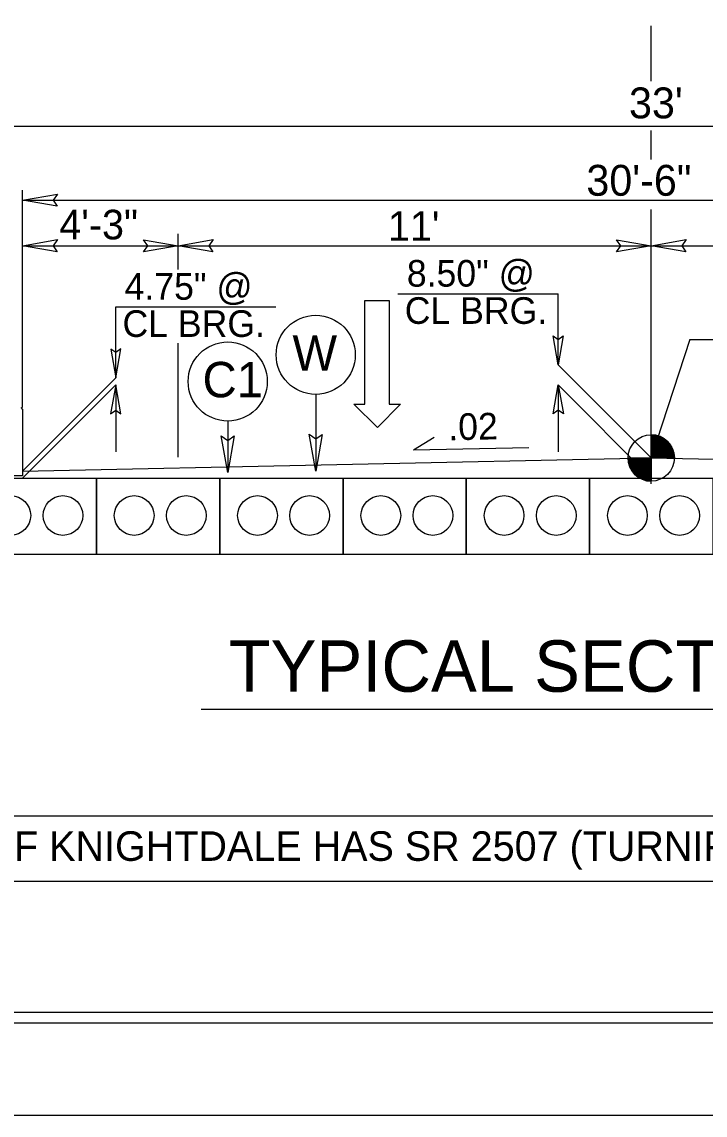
# Model space of a CAD drawing. Extents: x 693533 to 693723, y 486383 to 486493.
# Drawn here: x 693602.77 to 693619.39, y 486383.31 to 486409.89 of the extents above; entities that cross this region are included whole.
import ezdxf

# ---------------------------------------------------------------- set-up
doc = ezdxf.new("R2010")
doc.units = 0
for name, color, linetype in [('Default', 7, 'Continuous'), ('Old_Level_1', 7, 'Continuous'), ('Old_Level_11', 7, 'Continuous'), ('Old_Level_28', 7, 'Continuous'), ('Old_Level_3', 7, 'Continuous'), ('Prop Dimension', 7, 'Continuous'), ('Prop Lane Arrow CELL', 7, 'Continuous'), ('Sheet Cutting Line CELL', 7, 'Continuous'), ('Sheet Plot Border Inside CELL', 7, 'Continuous'), ('Sheet Plot Border Outside CELL', 7, 'Continuous'), ('Sheet Typical CELL', 7, 'Continuous'), ('Typical Bridge Rail Two Bar CELL', 7, 'Continuous'), ('Typical ID Circle CELL', 7, 'Continuous'), ('Typical Pavement Slope Information CELL', 7, 'Continuous'), ('Typical Terminator CELL', 7, 'Continuous'), ('Typical Text ID Circle CELL', 7, 'Continuous')]:
    doc.layers.add(name, color=color, linetype=linetype)

msp = doc.modelspace()

# ---------------------------------------------------------------- linework, layer by layer
at = {"layer": 'Default'}
for p, q in [((693618.081, 486408.451), (693618.081, 486409.801)), ((693618.081, 486406.545), (693618.081, 486407.256)), ((693618.081, 486398.664), (693618.081, 486405.329))]:
    msp.add_line(p, q, dxfattribs=at)
at = {"layer": 'Old_Level_1'}
msp.add_line((693607.128, 486393.188), (693629.755, 486393.188), dxfattribs=at)
msp.add_lwpolyline([(693595.018, 486390.588), (693644.204, 486390.588), (693644.204, 486388.993), (693595.018, 486388.993)], close=True, dxfattribs=at)
at = {"layer": 'Old_Level_28'}
for p, q in [((693601.581, 486407.359), (693634.581, 486407.359)), ((693602.787, 486400.52), (693602.787, 486405.801)), ((693602.787, 486405.557), (693633.374, 486405.557)), ((693606.574, 486403.872), (693606.574, 486404.74)), ((693602.787, 486404.451), (693606.574, 486404.451)), ((693606.574, 486404.451), (693618.081, 486404.451)), ((693618.081, 486404.451), (693629.081, 486404.451)), ((693606.574, 486399.312), (693606.574, 486402.086)), ((693619.016, 486402.168), (693618.081, 486399.291)), ((693619.016, 486402.168), (693623.462, 486402.168)), ((693618.081, 486399.291), (693618.081, 486399.853)), ((693602.787, 486398.972), (693618.081, 486399.291)), ((693617.518, 486399.291), (693618.081, 486399.291)), ((693618.079, 486398.728), (693618.081, 486399.291)), ((693618.081, 486399.291), (693618.079, 486398.728)), ((693618.081, 486399.291), (693633.374, 486398.972)), ((693618.643, 486399.291), (693618.081, 486399.291))]:
    msp.add_line(p, q, dxfattribs=at)
for points in [[(693603.631, 486405.412), (693602.787, 486405.557), (693603.636, 486405.707), (693603.528, 486405.557)], [(693603.631, 486404.305), (693602.787, 486404.451), (693603.636, 486404.601), (693603.528, 486404.451)], [(693605.731, 486404.596), (693606.574, 486404.451), (693605.726, 486404.301), (693605.834, 486404.451)], [(693607.418, 486404.305), (693606.574, 486404.451), (693607.423, 486404.601), (693607.315, 486404.451)], [(693617.237, 486404.596), (693618.081, 486404.451), (693617.232, 486404.301), (693617.34, 486404.451)], [(693618.924, 486404.305), (693618.081, 486404.451), (693618.929, 486404.601), (693618.821, 486404.451)], [(693601.581, 486398.804), (693604.581, 486398.804), (693604.581, 486396.944), (693601.581, 486396.944)], [(693604.581, 486398.804), (693607.581, 486398.804), (693607.581, 486396.944), (693604.581, 486396.944)], [(693607.581, 486398.804), (693610.581, 486398.804), (693610.581, 486396.944), (693607.581, 486396.944)], [(693610.581, 486398.804), (693613.581, 486398.804), (693613.581, 486396.944), (693610.581, 486396.944)], [(693613.581, 486398.804), (693616.581, 486398.804), (693616.581, 486396.944), (693613.581, 486396.944)], [(693616.581, 486398.804), (693619.581, 486398.804), (693619.581, 486396.944), (693616.581, 486396.944)]]:
    msp.add_lwpolyline(points, close=True, dxfattribs=at)
for points in [[(693618.086, 486399.853), (693618.086, 486399.853), (693618.086, 486399.291)], [(693618.097, 486399.853), (693618.097, 486399.291)], [(693618.108, 486399.852), (693618.108, 486399.291)], [(693618.119, 486399.852), (693618.119, 486399.291)], [(693618.131, 486399.851), (693618.131, 486399.291)], [(693618.142, 486399.849), (693618.142, 486399.291)], [(693618.153, 486399.848), (693618.153, 486399.291)], [(693618.164, 486399.847), (693618.164, 486399.291)], [(693618.176, 486399.846), (693618.176, 486399.291)], [(693618.187, 486399.843), (693618.187, 486399.291)], [(693618.198, 486399.841), (693618.198, 486399.291)], [(693618.209, 486399.838), (693618.209, 486399.291)], [(693618.221, 486399.836), (693618.221, 486399.291)], [(693618.232, 486399.832), (693618.232, 486399.291)], [(693618.243, 486399.829), (693618.243, 486399.291)], [(693618.254, 486399.826), (693618.254, 486399.291)], [(693618.266, 486399.822), (693618.266, 486399.291)], [(693618.277, 486399.818), (693618.277, 486399.291)], [(693618.288, 486399.813), (693618.288, 486399.291)], [(693618.299, 486399.808), (693618.299, 486399.291)], [(693618.311, 486399.803), (693618.311, 486399.291)], [(693618.322, 486399.798), (693618.322, 486399.291)], [(693618.333, 486399.793), (693618.333, 486399.291)], [(693618.344, 486399.787), (693618.344, 486399.291)], [(693618.356, 486399.781), (693618.356, 486399.291)], [(693618.367, 486399.774), (693618.367, 486399.291)], [(693618.378, 486399.768), (693618.378, 486399.291)], [(693618.389, 486399.761), (693618.389, 486399.291)], [(693618.401, 486399.753), (693618.401, 486399.291)], [(693618.412, 486399.744), (693618.412, 486399.291)], [(693618.423, 486399.737), (693618.423, 486399.291)], [(693618.434, 486399.728), (693618.434, 486399.291)], [(693618.446, 486399.718), (693618.446, 486399.291)], [(693618.457, 486399.708), (693618.457, 486399.291)], [(693618.468, 486399.698), (693618.468, 486399.291)], [(693618.479, 486399.687), (693618.479, 486399.291)], [(693618.491, 486399.676), (693618.491, 486399.291)], [(693618.502, 486399.663), (693618.502, 486399.291)], [(693618.513, 486399.649), (693618.513, 486399.291)], [(693618.524, 486399.636), (693618.524, 486399.291)], [(693618.536, 486399.621), (693618.536, 486399.291)], [(693618.547, 486399.604), (693618.547, 486399.291)], [(693618.558, 486399.587), (693618.558, 486399.291)], [(693618.569, 486399.568), (693618.569, 486399.291)], [(693618.581, 486399.548), (693618.581, 486399.291)], [(693618.592, 486399.524), (693618.592, 486399.291)], [(693618.603, 486399.498), (693618.603, 486399.291)], [(693618.614, 486399.467), (693618.614, 486399.291)], [(693618.626, 486399.428), (693618.626, 486399.291)], [(693618.637, 486399.371), (693618.637, 486399.291)], [(693617.521, 486399.291), (693617.521, 486399.229)], [(693617.532, 486399.291), (693617.532, 486399.163)], [(693617.543, 486399.291), (693617.543, 486399.123)], [(693617.554, 486399.291), (693617.554, 486399.089)], [(693617.566, 486399.291), (693617.566, 486399.063)], [(693617.577, 486399.291), (693617.577, 486399.039)], [(693617.588, 486399.291), (693617.588, 486399.018)], [(693617.599, 486399.291), (693617.599, 486398.998)], [(693617.611, 486399.291), (693617.611, 486398.981)], [(693617.622, 486399.291), (693617.622, 486398.964)], [(693617.633, 486399.291), (693617.633, 486398.949)], [(693617.644, 486399.291), (693617.644, 486398.936)], [(693617.656, 486399.291), (693617.656, 486398.922)], [(693617.667, 486399.291), (693617.667, 486398.909)], [(693617.678, 486399.291), (693617.678, 486398.897)], [(693617.689, 486399.291), (693617.689, 486398.886)], [(693617.701, 486399.291), (693617.701, 486398.876)], [(693617.712, 486399.291), (693617.712, 486398.866)], [(693617.723, 486399.291), (693617.723, 486398.856)], [(693617.734, 486399.291), (693617.734, 486398.847)], [(693617.746, 486399.291), (693617.746, 486398.838)], [(693617.757, 486399.291), (693617.757, 486398.831)], [(693617.768, 486399.291), (693617.768, 486398.823)], [(693617.779, 486399.291), (693617.779, 486398.816)], [(693617.791, 486399.291), (693617.791, 486398.808)], [(693617.802, 486399.291), (693617.802, 486398.802)], [(693617.813, 486399.291), (693617.813, 486398.796)], [(693617.824, 486399.291), (693617.824, 486398.789)], [(693617.836, 486399.291), (693617.836, 486398.784)], [(693617.847, 486399.291), (693617.847, 486398.779)], [(693617.858, 486399.291), (693617.858, 486398.774)], [(693617.869, 486399.291), (693617.869, 486398.769)], [(693617.881, 486399.291), (693617.881, 486398.764)], [(693617.892, 486399.291), (693617.892, 486398.761)], [(693617.903, 486399.291), (693617.903, 486398.757)], [(693617.914, 486399.291), (693617.914, 486398.753)], [(693617.926, 486399.291), (693617.926, 486398.751)], [(693617.937, 486399.291), (693617.937, 486398.747)], [(693617.948, 486399.291), (693617.948, 486398.744)], [(693617.959, 486399.291), (693617.959, 486398.742)], [(693617.971, 486399.291), (693617.971, 486398.739)], [(693617.982, 486399.291), (693617.982, 486398.737)], [(693617.993, 486399.291), (693617.993, 486398.736)], [(693618.004, 486399.291), (693618.004, 486398.733)], [(693618.016, 486399.291), (693618.016, 486398.732)], [(693618.027, 486399.291), (693618.027, 486398.731)], [(693618.038, 486399.291), (693618.038, 486398.729)], [(693618.049, 486399.291), (693618.049, 486398.729)], [(693618.061, 486399.291), (693618.061, 486398.728)], [(693618.072, 486399.291), (693618.072, 486398.728), (693618.072, 486398.728)]]:
    msp.add_lwpolyline(points, dxfattribs=at)
for centre, radius in [((693618.08, 486399.291), 0.563), ((693602.501, 486397.892), 0.483), ((693603.769, 486397.892), 0.483), ((693605.501, 486397.892), 0.483), ((693606.769, 486397.892), 0.483), ((693608.501, 486397.892), 0.483), ((693609.769, 486397.892), 0.483), ((693611.501, 486397.892), 0.483), ((693612.769, 486397.892), 0.483), ((693614.501, 486397.892), 0.483), ((693615.769, 486397.892), 0.483), ((693617.501, 486397.892), 0.483), ((693618.769, 486397.892), 0.483)]:
    msp.add_circle(centre, radius, dxfattribs=at)
for start, end in [(359.9905, 89.9905), (179.9905, 269.9905)]:
    msp.add_arc((693618.08, 486399.291), 0.563, start, end, dxfattribs=at)
at = {"layer": 'Prop Dimension'}
for p, q in [((693611.917, 486403.281), (693615.816, 486403.281)), ((693615.816, 486401.555), (693615.816, 486403.281)), ((693605.052, 486401.237), (693605.052, 486402.962)), ((693605.052, 486402.962), (693608.95, 486402.962)), ((693615.816, 486401.555), (693618.081, 486399.291)), ((693605.052, 486401.237), (693602.787, 486398.972)), ((693605.052, 486401.069), (693602.787, 486398.804)), ((693605.052, 486401.069), (693605.052, 486399.439)), ((693615.816, 486401.069), (693618.081, 486398.804)), ((693615.816, 486401.069), (693615.816, 486399.439))]:
    msp.add_line(p, q, dxfattribs=at)
at = {"layer": 'Prop Lane Arrow CELL'}
for p, q in [((693611.114, 486400.603), (693611.114, 486403.123)), ((693611.114, 486403.123), (693611.708, 486403.123)), ((693611.708, 486403.123), (693611.708, 486400.603)), ((693611.42, 486400.036), (693610.844, 486400.603)), ((693610.844, 486400.603), (693611.114, 486400.603)), ((693611.978, 486400.603), (693611.42, 486400.036)), ((693611.708, 486400.603), (693611.978, 486400.603))]:
    msp.add_line(p, q, dxfattribs=at)
at = {"layer": 'Sheet Cutting Line CELL'}
msp.add_line((693532.659, 486383.314), (693701.059, 486383.314), dxfattribs=at)
at = {"layer": 'Sheet Plot Border Inside CELL'}
msp.add_lwpolyline([(693700.609, 486491.069), (693533.959, 486491.069), (693533.959, 486385.559), (693700.609, 486385.559)], close=True, dxfattribs=at)
at = {"layer": 'Sheet Plot Border Outside CELL'}
msp.add_lwpolyline([(693701.059, 486493.314), (693532.659, 486493.314), (693532.659, 486383.314), (693701.059, 486383.314)], close=True, dxfattribs=at)
at = {"layer": 'Sheet Typical CELL'}
msp.add_lwpolyline([(693699.359, 486490.814), (693549.359, 486490.814), (693549.359, 486385.814), (693699.359, 486385.814)], close=True, dxfattribs=at)
at = {"layer": 'Typical Bridge Rail Two Bar CELL'}
for p, q in [((693602.74, 486400.52), (693602.787, 486400.472)), ((693602.787, 486400.472), (693602.787, 486398.856)), ((693602.787, 486398.856), (693601.707, 486398.856))]:
    msp.add_line(p, q, dxfattribs=at)
at = {"layer": 'Typical ID Circle CELL'}
for p, q in [((693609.917, 486400.837), (693609.917, 486398.971)), ((693607.777, 486400.188), (693607.777, 486398.936))]:
    msp.add_line(p, q, dxfattribs=at)
for centre in [(693609.917, 486401.799), (693607.777, 486401.15)]:
    msp.add_circle(centre, 0.962, dxfattribs=at)
at = {"layer": 'Typical Pavement Slope Information CELL'}
for q in [(693612.795, 486399.794), (693615.104, 486399.549)]:
    msp.add_line((693612.297, 486399.493), q, dxfattribs=at)
at = {"layer": 'Typical Terminator CELL'}
for points in [[(693615.937, 486402.258), (693615.816, 486401.555), (693615.691, 486402.262), (693615.816, 486402.173)], [(693604.931, 486401.94), (693605.052, 486401.237), (693605.177, 486401.944), (693605.052, 486401.854)], [(693605.173, 486400.366), (693605.052, 486401.069), (693604.927, 486400.362), (693605.052, 486400.452)], [(693615.695, 486400.366), (693615.816, 486401.069), (693615.941, 486400.362), (693615.816, 486400.452)], [(693607.93, 486399.826), (693607.777, 486398.936), (693607.618, 486399.831), (693607.777, 486399.717)], [(693610.071, 486399.862), (693609.917, 486398.971), (693609.759, 486399.867), (693609.917, 486399.753)]]:
    msp.add_lwpolyline(points, close=True, dxfattribs=at)

# ---------------------------------------------------------------- texts
at = {"layer": 'Old_Level_11'}
for s, p in [("33'", (693617.539, 486407.549)), ('30\'-6"', (693616.502, 486405.667))]:
    msp.add_text(s, height=0.75, dxfattribs=at).set_placement(p)
at = {"layer": 'Old_Level_28'}
for s, p in [('4\'-3"', (693603.68, 486404.607)), ("11'", (693611.674, 486404.571))]:
    msp.add_text(s, height=0.7188, dxfattribs=at).set_placement(p)
msp.add_text('NOTE: TOWN OF KNIGHTDALE HAS SR 2507 (TURNIPSEED ROAD) DESIGNATED A LOCAL BIKE ROUTE.', height=0.71875, rotation=360, dxfattribs=at).set_placement((693595.424, 486389.496))
at = {"layer": 'Old_Level_3'}
msp.add_text('TYPICAL SECTION NO.  ', height=1.25, dxfattribs=at).set_placement((693607.799, 486393.607))
at = {"layer": 'Prop Dimension'}
for s, p in [('8.50" @', (693612.134, 486403.457)), ('4.75" @', (693605.268, 486403.138)), ('CL BRG.', (693612.083, 486402.552)), ('CL BRG.', (693605.217, 486402.234))]:
    msp.add_text(s, height=0.6476, rotation=360, dxfattribs=at).set_placement(p)
at = {"layer": 'Typical Pavement Slope Information CELL'}
msp.add_text('.02', height=0.6476, rotation=1.1459, dxfattribs=at).set_placement((693613.149, 486399.721))
at = {"layer": 'Typical Text ID Circle CELL'}
for s, height, p in [('W', 0.861, (693609.351, 486401.414)), ('C1', 0.8608, (693607.164, 486400.766))]:
    msp.add_text(s, height=height, dxfattribs=at).set_placement(p)

doc.saveas('drawing.dxf')
